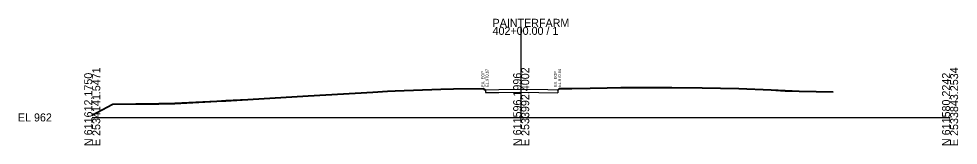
# Model space of a CAD drawing. Extents: x -26 to 453, y 80 to 2034.
# Drawn here: x -25.7 to 302.8, y 1990.3 to 2034.4 of the extents above; entities that cross this region are included whole.
import ezdxf

# ---------------------------------------------------------------- set-up
doc = ezdxf.new("R2010")
doc.units = 0
for name, color, linetype in [('DESIGN - SHEET - Light Grid', 7, 'Continuous'), ('SURVEY - GROUND - Bottom of Topsoil Layer', 7, 'Continuous'), ('SURVEY - GROUND - Existing Pavement Layer', 7, 'Continuous'), ('SURVEY - GROUND - Existing Pavement Text', 7, 'Continuous'), ('SURVEY - GROUND - Top of Ground', 7, 'Continuous')]:
    doc.layers.add(name, color=color, linetype=linetype)

msp = doc.modelspace()

# ---------------------------------------------------------------- linework, layer by layer
at = {"layer": 'DESIGN - SHEET - Light Grid'}
for p, q in [((150, 2000), (150, 2031.62)), ((0, 2000), (150, 2000)), ((150, 2000), (300, 2000))]:
    msp.add_line(p, q, dxfattribs=at)
at = {"layer": 'SURVEY - GROUND - Bottom of Topsoil Layer'}
for p, q in [((54.44, 2006.11), (75.53, 2007.41)), ((75.53, 2007.41), (98.07, 2008.69)), ((98.07, 2008.69), (103.22, 2009.02)), ((103.22, 2009.02), (105.9, 2009.13)), ((105.9, 2009.13), (121.96, 2009.73)), ((121.96, 2009.73), (126.31, 2009.85)), ((126.31, 2009.85), (136.8, 2009.93)), ((136.8, 2009.93), (137.49, 2009.42)), ((137.49, 2009.42), (137.49, 2009.67)), ((162.79, 2009.41), (163.43, 2009.93)), ((162.79, 2009.41), (162.79, 2009.66)), ((163.43, 2009.93), (167.66, 2009.98)), ((167.66, 2009.98), (174.12, 2010.09)), ((174.12, 2010.09), (180.05, 2010.25)), ((180.05, 2010.25), (184.8, 2010.28)), ((184.8, 2010.28), (202.67, 2010.29)), ((202.67, 2010.29), (213.29, 2010.19)), ((213.29, 2010.19), (226.14, 2010.02)), ((226.14, 2010.02), (237.43, 2009.53)), ((237.43, 2009.53), (242.28, 2009.21)), ((242.28, 2009.21), (247.25, 2009)), ((247.25, 2009), (259.14, 2008.83)), ((0, 2000.7), (7.25, 2004.48)), ((7.25, 2004.48), (23.33, 2004.68)), ((23.33, 2004.68), (26.54, 2004.74)), ((26.54, 2004.74), (28.91, 2004.79)), ((28.91, 2004.79), (43.62, 2005.55)), ((43.62, 2005.55), (46.74, 2005.72)), ((46.74, 2005.72), (54.44, 2006.11))]:
    msp.add_line(p, q, dxfattribs=at)
at = {"layer": 'SURVEY - GROUND - Existing Pavement Layer'}
for p, q in [((137.49, 2009.67), (137.49, 2008.67)), ((162.79, 2009.66), (162.79, 2008.64))]:
    msp.add_line(p, q, dxfattribs=at)
msp.add_lwpolyline([(137.49, 2008.67), (142.15, 2008.73), (149.56, 2008.82), (162.79, 2008.64)], dxfattribs=at)
at = {"layer": 'SURVEY - GROUND - Top of Ground'}
msp.add_lwpolyline([(0, 2000.95), (7.25, 2004.73), (23.33, 2004.93), (26.54, 2004.99), (28.91, 2005.04), (43.62, 2005.8), (46.74, 2005.97), (54.44, 2006.36), (75.53, 2007.66), (98.07, 2008.94), (103.22, 2009.27), (105.9, 2009.38), (121.96, 2009.98), (126.31, 2010.1), (136.8, 2010.18), (137.49, 2009.67), (142.14, 2009.73), (149.56, 2009.82), (150, 2009.81), (159.36, 2009.69), (162.79, 2009.66), (163.43, 2010.18), (167.66, 2010.23), (174.12, 2010.34), (180.05, 2010.5), (184.8, 2010.53), (202.67, 2010.54), (213.29, 2010.44), (226.14, 2010.27), (237.43, 2009.78), (242.28, 2009.46), (247.25, 2009.25), (259.14, 2009.08)], dxfattribs=at)

# ---------------------------------------------------------------- texts
at = {"layer": 'DESIGN - SHEET - Light Grid'}
for s, p in [('PAINTERFARM', (140, 2031.62)), ('402+00.00 / 1', (140, 2028.82)), ('EL 962', (-26, 1998.6))]:
    msp.add_text(s, height=2.8, dxfattribs=at).set_placement(p)
for s, p in [('E 2534141.5471', (2.8, 1990)), ('E 2533992.4002', (152.8, 1990)), ('E 2533843.2534', (302.8, 1990)), ('N 611612.1750', (0, 1990)), ('N 611596.1996', (150, 1990)), ('N 611580.2242', (300, 1990))]:
    msp.add_text(s, height=2.8, rotation=90, dxfattribs=at).set_placement(p)
at = {"layer": 'SURVEY - GROUND - Existing Pavement Text'}
for s, p in [('EX. EOP', (137.09, 2010.65)), ('EL.970.67', (138.59, 2010.65)), ('EX. EOP', (162.44, 2010.65)), ('EL.970.64', (163.94, 2010.65))]:
    msp.add_text(s, height=1, rotation=90, dxfattribs=at).set_placement(p)

doc.saveas('drawing.dxf')
